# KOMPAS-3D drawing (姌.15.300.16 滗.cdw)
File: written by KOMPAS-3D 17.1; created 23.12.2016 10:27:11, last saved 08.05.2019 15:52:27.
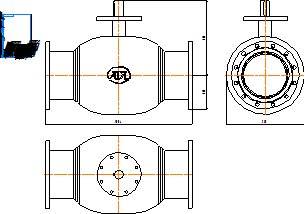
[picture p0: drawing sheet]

Sheet 1: A4, portrait

Title block, sheet 1: name: КШ.15.300.16 фф; material: Внимание! Данный продукт является объектом авторского права ООО «Торговый Дом АДЛ». / Запрещается изменение, копирование, распространение / (в том числе путем копирования на другие сайты и ресурсы в Интернете) / или любое иное использование информации и объектов без предварительного / согласия правообладателя (ООО «Торговый Дом АДЛ»).; sheets: 1; organisation: ООО "Торговый дом АДЛ"; sheet format: A4; stored path: C:\Users\tra\Desktop\2д чертежи\Шаровые краны БИВАЛ\КШ_Бивал_серия_14_15\KOMPAS_2D\КШ.15.300.16 фф.cdw

Views: Вид 1, Проекционный вид 2, Проекционный вид 3
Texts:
  Klimkovich
  ADL
Dimensions and other numbers on the sheet: 1004; 505; 230; 530; 1:1; 1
